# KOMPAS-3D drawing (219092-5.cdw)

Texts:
  Курсова робота
  Стріла
  Бабіч
  Текст на чертеже
  Размерные надписи
  Шероховатость
  Линия-выноска #1
  Линия-выноска #2
  Линия-выноска #3
  Отклонения формы и база
  Заголовок таблицы
  Ячейка таблицы
  Стрелка вида
  Обозначение изменения
  Фигурная скобка
  Номер узла
  Марка координационной оси
  VRCB
  Выносная надпись
  Обозначение узла
  Марка/позиционное обозначение с линией-выноской
  Марка/позиционное обозначение на линии
  Марка/позиционное обозначение без линии-выноски
  Горбатюк
  Курсова робота-
Dimensions and other numbers on the sheet: 7; 29100; 4800; 17300; 11800; 6800; 1800; 2500; 1:50; 1; 0; 2; 3; 4; 5; 6; 8; 9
